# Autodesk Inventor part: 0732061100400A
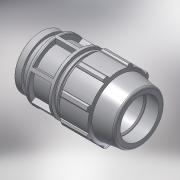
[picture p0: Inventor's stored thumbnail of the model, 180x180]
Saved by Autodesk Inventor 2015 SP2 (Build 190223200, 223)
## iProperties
Created: 2017-02
Part Number: 0732061100400A
Material: PVC-Piping
Description: PLASSON SHOULDERED ADAPTOR 110-4"
Document SubType Name: Modeling
Designer: KIM
Mass: 92.6774 g
Surface Area: 199.44 cm^2
Volume: 66.1981 cm^3
Density: 1.4 g/cm^3
Appearance: Smooth - White
Author: KIM
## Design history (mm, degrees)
derived "87320.ipt"
feature "Solid1::87320.ipt"
tag "TaggingFeature1"
body "Solid1"
other parameters: "d4" = 36.42857, "d5" = 51, "d7" = 181, "d8" = 135.75, "d9" = 36.42857, "d11" = 9.10714, "d12" = 144.8, "d13" = 120 deg, "d15" = 8 deg, "d16" = 162.9, "d18" = 5, "d19" = 35 deg, "d20" = 17.5 deg, "d21" = 168.33, "d23" = 0, "d25" = 360 deg, "d27" = 3.62, "d34" = 9.05, "d36" = 0, "d42" = 76.5, "d43" = 5.43, "d46" = 3, "d49" = 213, "d51" = 255, "d53" = 2, "d55" = 360 deg, "d57" = 123, "d59" = 51, "d61" = 110.7, "d62" = 16, "d64" = 6.57143, "d66" = 154.755, "d67" = 6.57143, "d70" = 86.1, "d71" = 73.8, "d73" = 6.15, "d74" = 16, "E_" = 181, "H_" = 255, "l_" = 213, "L_" = 16, "B_" = 123, "d63" = 26.28571, "d72" = 18.45
